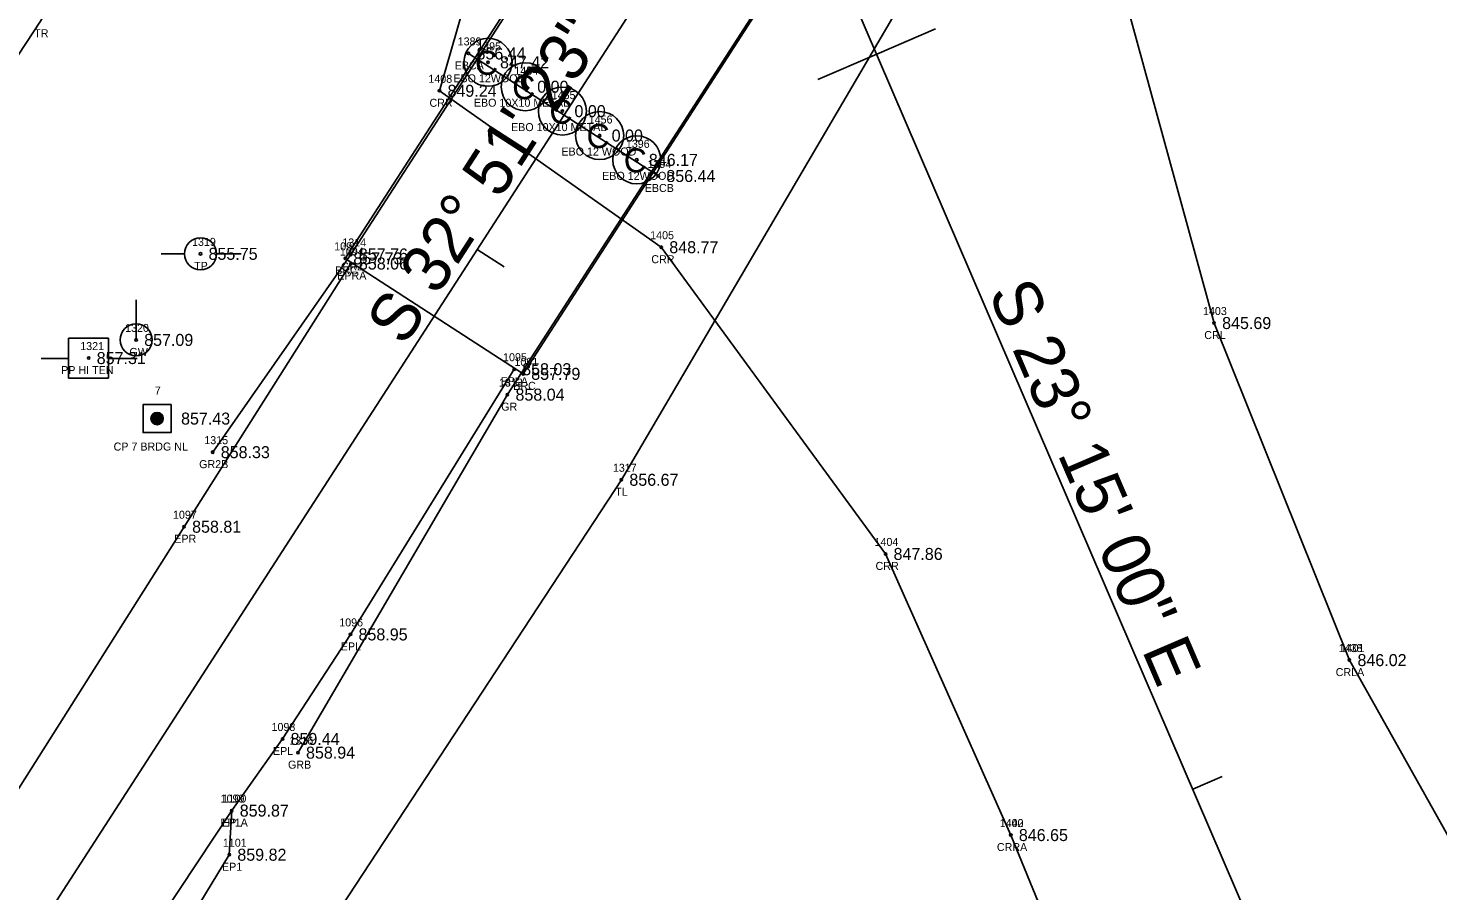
# Model space of a CAD drawing. Extents: x 1393163 to 1398407, y 1072670 to 1074651.
# Drawn here: x 1395829.2 to 1396005.3, y 1073833.3 to 1073941.1 of the extents above; entities that cross this region are included whole.
import ezdxf

# ---------------------------------------------------------------- set-up
doc = ezdxf.new("R2010")
doc.units = 0
for name, color, linetype in [('RD_EX_Bridge', 7, 'Continuous'), ('RD_EX_Bridge_txCode', 7, 'Continuous'), ('RD_EX_GuardRail', 7, 'Continuous'), ('RD_EX_GuardRail_txCode', 7, 'Continuous'), ('RD_EX_H2O', 7, 'Continuous'), ('RD_EX_H2O_txCode', 7, 'Continuous'), ('RD_EX_Road', 7, 'Continuous'), ('RD_EX_Road_txCode', 7, 'Continuous'), ('RD_EX_TX_Bridge_ELEV', 7, 'Continuous'), ('RD_EX_TX_GuardRail_ELEV', 7, 'Continuous'), ('RD_EX_TX_H2O_ELEV', 7, 'Continuous'), ('RD_EX_TX_Road_ELEV', 7, 'Continuous'), ('RD_EX_TX_UT_ELEV', 7, 'Continuous'), ('RD_EX_TX_VEG_ELEV', 7, 'Continuous'), ('RD_EX_UT', 7, 'Continuous'), ('RD_EX_UT_txCode', 7, 'Continuous'), ('RD_EX_VEG', 7, 'Continuous'), ('RD_EX_VEG_txCode', 7, 'Continuous'), ('RD_HC_Cl', 7, 'Continuous'), ('RD_HC_Data', 7, 'Continuous'), ('RD_HC_Data_Tic', 7, 'Continuous'), ('RD_HC_Survey', 7, 'Continuous'), ('RD_HC_Survey_ELEV', 7, 'Continuous'), ('RD_HC_Survey_txCode', 7, 'Continuous'), ('RD_SMD_Locator', 7, 'Continuous')]:
    doc.layers.add(name, color=color, linetype=linetype)

msp = doc.modelspace()

# ---------------------------------------------------------------- linework, layer by layer
at = {"layer": 'RD_EX_Bridge'}
msp.add_line((1395884.24, 1073937.97), (1395907.96, 1073922.65), dxfattribs=at)
msp.add_lwpolyline([(1395933.91, 1074013), (1395956.09, 1073998.72), (1395891.08, 1073897.92), (1395868.85, 1073912.35), (1395933.91, 1074013)], dxfattribs=at)
for centre in [(1395886.68, 1073936.86), (1395891.33, 1073933.81), (1395895.98, 1073930.76), (1395900.63, 1073927.71), (1395905.27, 1073924.67)]:
    msp.add_circle(centre, 3, dxfattribs=at)
at = {"layer": 'RD_EX_GuardRail'}
for points in [[(1396016.92, 1074142.31), (1395982.2, 1074087.63), (1395935.47, 1074014.91), (1395869.54, 1073912.84), (1395852.29, 1073888.13)], [(1395985.54, 1074043.44), (1395921.29, 1073945.23), (1395889.11, 1073895.32), (1395862.94, 1073850.57)]]:
    msp.add_lwpolyline(points, dxfattribs=at)
at = {"layer": 'RD_EX_H2O'}
for points in [[(1395994.31, 1073862.14), (1395977.4, 1073904.27), (1395963.85, 1073953.72), (1395946.27, 1073971.77), (1395916.4, 1074002.54), (1395890.56, 1074039.92), (1395847.47, 1074083.11), (1395801.13, 1074111.33), (1395786.04, 1074175.28), (1395797.31, 1074211.4), (1395811.45, 1074270.55), (1395842.05, 1074318.44), (1395857.75, 1074334.75)], [(1395952, 1073840.27), (1395936.35, 1073875.41), (1395908.33, 1073913.75), (1395880.62, 1073933.3), (1395888.13, 1073959.38), (1395867.11, 1073990.5)], [(1395994.31, 1073862.14), (1396016.23, 1073823.05), (1396049.51, 1073777.43), (1396097.83, 1073746.6), (1396142.35, 1073713.94), (1396184.8, 1073664), (1396205.08, 1073599.52), (1396208.44, 1073572.95)], [(1395952, 1073840.27), (1395978.45, 1073775.7), (1396021.08, 1073745.03), (1396057.91, 1073712.79), (1396093.73, 1073686.58), (1396133.33, 1073631.65), (1396141.56, 1073591.93), (1396145.07, 1073563.23)]]:
    msp.add_lwpolyline(points, dxfattribs=at)
at = {"layer": 'RD_EX_Road'}
for points in [[(1395869.55, 1073911.71), (1395848.71, 1073878.81), (1395821.89, 1073836.43), (1395795.02, 1073794.57), (1395768.15, 1073753.29), (1395739.4, 1073711.73), (1395711.25, 1073671.91), (1395680.67, 1073632.3), (1395648.91, 1073595.47), (1395613.89, 1073559.5), (1395578.15, 1073528.43), (1395538.64, 1073499.26)], [(1395889.95, 1073898.5), (1395869.5, 1073865.35), (1395861.01, 1073852.28), (1395854.66, 1073843.33), (1395841.6, 1073823.61), (1395818.72, 1073786.86), (1395788.22, 1073740.4), (1395759.3, 1073697.79), (1395730.49, 1073656.98), (1395699.68, 1073617), (1395667.2, 1073579.48), (1395631.87, 1073543.45), (1395592.83, 1073509.92), (1395550.91, 1073478.97)], [(1395854.66, 1073843.33), (1395854.36, 1073837.81), (1395844.77, 1073821.99), (1395818.72, 1073786.86)]]:
    msp.add_lwpolyline(points, dxfattribs=at)
at = {"layer": 'RD_EX_UT'}
for p, q in [((1395845.83, 1073912.93), (1395848.76, 1073912.93)), ((1395852.76, 1073912.93), (1395855.83, 1073912.93)), ((1395842.72, 1073902.16), (1395842.72, 1073907.16)), ((1395839.28, 1073902.4), (1395834.28, 1073902.4)), ((1395834.28, 1073902.4), (1395834.28, 1073897.4)), ((1395839.28, 1073897.4), (1395839.28, 1073902.4)), ((1395830.85, 1073899.83), (1395834.32, 1073899.83)), ((1395839.21, 1073899.83), (1395842.85, 1073899.83)), ((1395834.28, 1073897.4), (1395839.28, 1073897.4))]:
    msp.add_line(p, q, dxfattribs=at)
for centre in [(1395850.76, 1073912.92), (1395842.72, 1073902.16)]:
    msp.add_circle(centre, 2, dxfattribs=at)
at = {"layer": 'RD_EX_VEG'}
for points in [[(1396352.77, 1074466.81), (1396307.45, 1074411.54), (1396264.81, 1074389.13), (1396223.65, 1074377.38), (1396189.41, 1074374.79), (1396152.48, 1074363.91), (1396104.93, 1074328.72), (1396084.67, 1074294.89), (1396058.15, 1074258), (1396032.64, 1074208.26), (1395942.76, 1074111.4), (1395907.95, 1074076.23), (1395890.22, 1074043.32), (1395830.78, 1073942), (1395722.32, 1073776.86), (1395650.71, 1073693.74), (1395598.01, 1073628.59), (1395527.38, 1073544.13)], [(1396669.03, 1074354.22), (1396616.02, 1074355.85), (1396573.77, 1074355.35), (1396526.61, 1074357.18), (1396479.56, 1074337.11), (1396434.19, 1074332.46), (1396381.24, 1074326.22), (1396336.08, 1074320.75), (1396275.81, 1074321.18), (1396244.15, 1074304.15), (1396202.15, 1074284.28), (1396132.57, 1074226.35), (1396098.86, 1074188.29), (1396070.36, 1074149.88), (1396041.42, 1074108.96), (1396016.11, 1074067.71), (1395987.17, 1074027.64), (1395903.34, 1073884.68), (1395772.36, 1073685.07), (1395714.36, 1073607.99), (1395678.43, 1073565.6), (1395644.57, 1073530.52), (1395600.99, 1073489.29), (1395561.12, 1073435.87)]]:
    msp.add_lwpolyline(points, dxfattribs=at)
at = {"layer": 'RD_HC_Cl'}
for p, q in [((1396041.52, 1074155.31), (1395744.21, 1073694.97)), ((1395921.6, 1073969.63), (1395997.49, 1073792.99))]:
    msp.add_line(p, q, dxfattribs=at)
at = {"layer": 'RD_HC_Data_Tic'}
for p, q in [((1395935.24, 1073937.87), (1395942.59, 1073941.03)), ((1395935.24, 1073937.87), (1395927.89, 1073934.71)), ((1395885.33, 1073913.46), (1395888.69, 1073911.29)), ((1395974.72, 1073845.99), (1395978.39, 1073847.57))]:
    msp.add_line(p, q, dxfattribs=at)
at = {"layer": 'RD_HC_Survey'}
for p, q in [((1395844.66, 1073891.96), (1395844.66, 1073892.7)), ((1395844.68, 1073891.92), (1395844.68, 1073892.74)), ((1395844.71, 1073891.88), (1395844.71, 1073892.78)), ((1395844.73, 1073891.85), (1395844.73, 1073892.81)), ((1395844.76, 1073891.82), (1395844.76, 1073892.84)), ((1395844.78, 1073891.79), (1395844.78, 1073892.87)), ((1395844.81, 1073891.77), (1395844.81, 1073892.89)), ((1395844.83, 1073891.75), (1395844.83, 1073892.92)), ((1395844.86, 1073891.73), (1395844.86, 1073892.94)), ((1395844.88, 1073891.71), (1395844.88, 1073892.95)), ((1395844.91, 1073891.69), (1395844.91, 1073892.97)), ((1395844.93, 1073891.67), (1395844.93, 1073892.99)), ((1395844.96, 1073891.66), (1395844.96, 1073893)), ((1395844.98, 1073891.65), (1395844.98, 1073893.02)), ((1395845.01, 1073891.63), (1395845.01, 1073893.03)), ((1395845.03, 1073891.62), (1395845.03, 1073893.04)), ((1395845.05, 1073891.61), (1395845.05, 1073893.05)), ((1395845.08, 1073891.6), (1395845.08, 1073893.06)), ((1395845.1, 1073891.6), (1395845.1, 1073893.07)), ((1395845.13, 1073891.59), (1395845.13, 1073893.07)), ((1395845.15, 1073891.58), (1395845.15, 1073893.08)), ((1395845.18, 1073891.58), (1395845.18, 1073893.08)), ((1395845.2, 1073891.57), (1395845.2, 1073893.09)), ((1395845.23, 1073891.57), (1395845.23, 1073893.09)), ((1395845.25, 1073891.57), (1395845.25, 1073893.1)), ((1395845.28, 1073891.56), (1395845.28, 1073893.1)), ((1395845.3, 1073891.56), (1395845.3, 1073893.1)), ((1395845.33, 1073891.56), (1395845.33, 1073893.1)), ((1395845.35, 1073891.56), (1395845.35, 1073893.1)), ((1395845.38, 1073891.56), (1395845.38, 1073893.1)), ((1395845.4, 1073891.56), (1395845.4, 1073893.1)), ((1395845.43, 1073891.57), (1395845.43, 1073893.09)), ((1395845.45, 1073891.57), (1395845.45, 1073893.09)), ((1395845.48, 1073891.57), (1395845.48, 1073893.09)), ((1395845.5, 1073891.58), (1395845.5, 1073893.08)), ((1395845.53, 1073891.59), (1395845.53, 1073893.08)), ((1395845.55, 1073891.59), (1395845.55, 1073893.07)), ((1395845.57, 1073891.6), (1395845.57, 1073893.06)), ((1395845.6, 1073891.61), (1395845.6, 1073893.05)), ((1395845.62, 1073891.62), (1395845.62, 1073893.04)), ((1395845.65, 1073891.63), (1395845.65, 1073893.03)), ((1395845.67, 1073891.64), (1395845.67, 1073893.02)), ((1395845.7, 1073891.65), (1395845.7, 1073893.01)), ((1395845.72, 1073891.67), (1395845.72, 1073892.99)), ((1395845.75, 1073891.68), (1395845.75, 1073892.98)), ((1395845.77, 1073891.7), (1395845.77, 1073892.96)), ((1395845.8, 1073891.72), (1395845.8, 1073892.94)), ((1395845.82, 1073891.74), (1395845.82, 1073892.93)), ((1395845.85, 1073891.76), (1395845.85, 1073892.9)), ((1395845.87, 1073891.78), (1395845.87, 1073892.88)), ((1395845.9, 1073891.81), (1395845.9, 1073892.86)), ((1395845.92, 1073891.83), (1395845.92, 1073892.83)), ((1395845.95, 1073891.87), (1395845.95, 1073892.8)), ((1395845.97, 1073891.9), (1395845.97, 1073892.76)), ((1395846, 1073891.94), (1395846, 1073892.72)), ((1395844.58, 1073892.15), (1395844.58, 1073892.51)), ((1395844.61, 1073892.07), (1395844.61, 1073892.59)), ((1395844.63, 1073892.01), (1395844.63, 1073892.65)), ((1395846.02, 1073891.98), (1395846.02, 1073892.68)), ((1395846.04, 1073892.04), (1395846.04, 1073892.62)), ((1395846.07, 1073892.11), (1395846.07, 1073892.55)), ((1395846.09, 1073892.22), (1395846.09, 1073892.44))]:
    msp.add_line(p, q, dxfattribs=at)
msp.add_lwpolyline([(1395847.08, 1073894.08), (1395843.58, 1073894.08), (1395843.58, 1073890.58), (1395847.08, 1073890.58)], close=True, dxfattribs=at)
msp.add_circle((1395845.33, 1073892.33), 0.769, dxfattribs=at)
at = {"layer": 'RD_SMD_Locator'}
for centre in [(1395884.24, 1073937.97), (1395886.68, 1073936.86), (1395880.62, 1073933.3), (1395891.33, 1073933.81), (1395895.98, 1073930.76), (1395900.63, 1073927.71), (1395905.27, 1073924.67), (1395907.96, 1073922.65), (1395908.33, 1073913.75), (1395850.76, 1073912.92), (1395868.85, 1073912.35), (1395869.54, 1073912.84), (1395869.55, 1073911.71), (1395977.4, 1073904.27), (1395842.72, 1073902.16), (1395836.79, 1073899.89), (1395889.95, 1073898.5), (1395891.08, 1073897.92), (1395889.11, 1073895.32), (1395845.33, 1073892.33), (1395852.29, 1073888.13), (1395903.34, 1073884.68), (1395848.71, 1073878.81), (1395936.35, 1073875.41), (1395869.5, 1073865.35), (1395994.31, 1073862.14), (1395994.31, 1073862.14), (1395861.01, 1073852.28), (1395862.94, 1073850.57), (1395854.66, 1073843.33), (1395854.66, 1073843.33), (1395952, 1073840.27), (1395952, 1073840.27), (1395854.36, 1073837.81)]:
    msp.add_circle(centre, 0.15, dxfattribs=at)

# ---------------------------------------------------------------- texts
at = {"layer": 'RD_EX_Bridge'}
for p in [(1395885.05, 1073935.3), (1395889.7, 1073932.25), (1395894.35, 1073929.2), (1395898.99, 1073926.15), (1395903.64, 1073923.1)]:
    msp.add_text('C', height=3, dxfattribs=at).set_placement(p)
at = {"layer": 'RD_EX_Bridge_txCode'}
for s, p in [('1389', (1395882.89, 1073938.97)), ('1395', (1395885.33, 1073938.36)), ('EBCA', (1395882.52, 1073935.97)), ('EBO 12WOOD', (1395882.35, 1073934.36)), ('1454', (1395889.98, 1073935.31)), ('1455', (1395894.63, 1073932.26)), ('EBO 10X10 METAL', (1395884.91, 1073931.31)), ('1456', (1395899.26, 1073929.21)), ('EBO 10X10 METAL', (1395889.56, 1073928.26)), ('EBO 12 WOOD', (1395895.85, 1073925.21)), ('1396', (1395903.9, 1073926.17)), ('1394', (1395906.62, 1073923.65)), ('EBO 12WOOD', (1395900.94, 1073922.17)), ('EBCB', (1395906.26, 1073920.65)), ('1092', (1395867.46, 1073913.35)), ('BRC', (1395867.59, 1073910.35)), ('1091', (1395889.98, 1073898.92)), ('BRC', (1395889.83, 1073895.92))]:
    msp.add_text(s, height=1, dxfattribs=at).set_placement(p)
at = {"layer": 'RD_EX_GuardRail_txCode'}
for s, p in [('1314', (1395868.48, 1073913.84)), ('GR2', (1395868.32, 1073910.84)), ('1313', (1395888.05, 1073896.32)), ('GR', (1395888.33, 1073893.32)), ('1315', (1395851.23, 1073889.13)), ('GR2B', (1395850.59, 1073886.13)), ('1316', (1395861.86, 1073851.57)), ('GRB', (1395861.69, 1073848.57))]:
    msp.add_text(s, height=1, dxfattribs=at).set_placement(p)
at = {"layer": 'RD_EX_H2O_txCode'}
for s, p in [('1408', (1395879.23, 1073934.3)), ('CRR', (1395879.37, 1073931.3)), ('1405', (1395906.94, 1073914.75)), ('CRR', (1395907.08, 1073911.75)), ('1403', (1395976.01, 1073905.27)), ('CRL', (1395976.17, 1073902.27)), ('1404', (1395934.97, 1073876.41)), ('CRR', (1395935.1, 1073873.41)), ('1438', (1395992.96, 1073863.14)), ('1401', (1395993.2, 1073863.14)), ('CRLA', (1395992.59, 1073860.14)), ('CRLA', (1395992.59, 1073860.14)), ('1402', (1395950.61, 1073841.27)), ('1440', (1395950.61, 1073841.27)), ('CRRA', (1395950.26, 1073838.27)), ('CRRA', (1395950.26, 1073838.27))]:
    msp.add_text(s, height=1, dxfattribs=at).set_placement(p)
at = {"layer": 'RD_EX_Road_txCode'}
for s, p in [('1094', (1395868.17, 1073912.71)), ('EPRA', (1395867.84, 1073909.71)), ('1095', (1395888.56, 1073899.5)), ('EPLA', (1395888.26, 1073896.5)), ('1097', (1395847.32, 1073879.81)), ('EPR', (1395847.48, 1073876.81)), ('1096', (1395868.09, 1073866.35)), ('EPL', (1395868.29, 1073863.35)), ('1098', (1395859.63, 1073853.28)), ('EPL', (1395859.81, 1073850.28)), ('1099', (1395853.27, 1073844.33)), ('1100', (1395853.51, 1073844.33)), ('EP1A', (1395853.25, 1073841.33)), ('EPL', (1395853.45, 1073841.33)), ('1101', (1395853.55, 1073838.81)), ('EP1', (1395853.44, 1073835.81))]:
    msp.add_text(s, height=1, dxfattribs=at).set_placement(p)
at = {"layer": 'RD_EX_TX_Bridge_ELEV'}
for s, p in [('856.44', (1395885.24, 1073937.22)), ('847.42', (1395888.18, 1073936.11)), ('0.00', (1395892.83, 1073933.06)), ('0.00', (1395897.48, 1073930.01)), ('0.00', (1395902.13, 1073926.96)), ('846.17', (1395906.77, 1073923.92)), ('856.44', (1395908.96, 1073921.9)), ('857.73', (1395869.85, 1073911.6)), ('857.79', (1395892.08, 1073897.17))]:
    msp.add_text(s, height=1.5, dxfattribs=at).set_placement(p)
at = {"layer": 'RD_EX_TX_GuardRail_ELEV'}
for s, p in [('857.76', (1395870.54, 1073912.09)), ('858.04', (1395890.11, 1073894.57)), ('858.33', (1395853.29, 1073887.38)), ('858.94', (1395863.94, 1073849.82))]:
    msp.add_text(s, height=1.5, dxfattribs=at).set_placement(p)
at = {"layer": 'RD_EX_TX_H2O_ELEV'}
for s, p in [('849.24', (1395881.62, 1073932.55)), ('848.77', (1395909.33, 1073913)), ('845.69', (1395978.4, 1073903.52)), ('847.86', (1395937.35, 1073874.66)), ('846.02', (1395995.31, 1073861.39)), ('846.02', (1395995.31, 1073861.39)), ('846.65', (1395953, 1073839.52)), ('846.65', (1395953, 1073839.52))]:
    msp.add_text(s, height=1.5, dxfattribs=at).set_placement(p)
at = {"layer": 'RD_EX_TX_Road_ELEV'}
for s, p in [('858.06', (1395870.55, 1073910.96)), ('858.03', (1395890.95, 1073897.75)), ('858.81', (1395849.71, 1073878.06)), ('858.95', (1395870.5, 1073864.6)), ('859.44', (1395862.01, 1073851.53)), ('859.87', (1395855.66, 1073842.58)), ('859.87', (1395855.66, 1073842.58)), ('859.82', (1395855.36, 1073837.06))]:
    msp.add_text(s, height=1.5, dxfattribs=at).set_placement(p)
at = {"layer": 'RD_EX_TX_UT_ELEV'}
for s, p in [('855.75', (1395851.76, 1073912.17)), ('857.09', (1395843.72, 1073901.41))]:
    msp.add_text(s, height=1.5, dxfattribs=at).set_placement(p)
at = {"layer": 'RD_EX_TX_VEG_ELEV'}
msp.add_text('856.67', height=1.5, dxfattribs=at).set_placement((1395904.34, 1073883.93))
at = {"layer": 'RD_EX_UT_txCode'}
for s, p in [('1319', (1395849.7, 1073913.92)), ('TP', (1395849.96, 1073910.92)), ('1320', (1395841.34, 1073903.16)), ('1321', (1395835.73, 1073900.89)), ('GW', (1395841.88, 1073900.16)), ('PP HI TEN', (1395833.35, 1073897.89))]:
    msp.add_text(s, height=1, dxfattribs=at).set_placement(p)
at = {"layer": 'RD_EX_VEG_txCode'}
for s, p in [('TR', (1395829.98, 1073940)), ('1317', (1395902.28, 1073885.68)), ('TL', (1395902.57, 1073882.68))]:
    msp.add_text(s, height=1, dxfattribs=at).set_placement(p)
at = {"layer": 'RD_HC_Data'}
for s, rotation, p in [('S 32%%d 51\' 23" W', 57.1437, (1395876.23, 1073901.21)), ('S 23%%d 15\' 00" E', 293.2499, (1395949.13, 1073908.07))]:
    msp.add_text(s, height=6, rotation=rotation, dxfattribs=at).set_placement(p)
at = {"layer": 'RD_HC_Survey_ELEV'}
for s, p in [('857.31', (1395837.79, 1073899.14)), ('857.43', (1395848.33, 1073891.58))]:
    msp.add_text(s, height=1.5, dxfattribs=at).set_placement(p)
at = {"layer": 'RD_HC_Survey_txCode'}
for s, p in [('7', (1395845.05, 1073895.33)), ('CP 7 BRDG NL', (1395839.9, 1073888.33))]:
    msp.add_text(s, height=1, dxfattribs=at).set_placement(p)

doc.saveas('drawing.dxf')
